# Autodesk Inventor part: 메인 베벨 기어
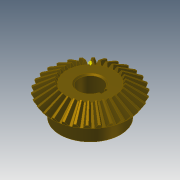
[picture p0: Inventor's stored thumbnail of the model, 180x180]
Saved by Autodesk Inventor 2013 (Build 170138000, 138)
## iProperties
Created: 2014-10
Part Number: 메인 베벨 기어
Material: 강철
Document SubType Name: Modeling
Designer: KYOUNG IL JANG
Categories: <?xml version="1.0" encoding="UTF-16"?> <MemberInstance><Categories><FamilyTemplate><FamilyTemplateParameter ValueType="xs:double" Id="1" ObjectReferenceKey="da
Mass: 269.24 g
Surface Area: 108.837 cm^2
Volume: 34.2981 cm^3
Density: 7.85 g/cm^3
CustomPartVersion: 1
Company: 한국ATC센터
Author: KYOUNG IL JANG
Revision Number: 1
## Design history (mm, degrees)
node "맨 위 점"
node "메쉬 평면2"
sketch "톱니 본체 스케치"
  geometry: L1 (0, 0)-(28.669, -21.997); L2 (28.669, -21.997)-(31.109, -18.336); L3 (31.109, -18.336)-(0, 0); L4 (30, -20)-(0, 0); L5 (17.219, -13.212)-(18.685, -11.013); L6 (28.669, -21.997)-(17.219, -13.212); L7 (31.109, -18.336)-(18.685, -11.013); L8 (0, -39.387)-(0, 6.564) reference; L9 (0, -20)-(31.109, -20)
  constraints: 16 end point, 4 point on line, 3 perpendicular, 2 collinear, 1 horizontal alignment, 1 vertical alignment
  dimensions: "d0" = 60 diameter of L4.start L8 (= da_de); "d1" = 57.33744 diameter of L1.end L8 (= da_dfe); "d2" = 62.2188 diameter of L2.end L8 (= da_dae); "d3" = 14.4 distance between parallel lines of L2 L5 (= da_b); "d4" = 18.3359 vertical distance of L2.end L1.start (= da_ve)
revolve "톱니 본체" sketch "톱니 본체 스케치" stored, may be unused: angle "d5" = 90 deg
node "시작점"
node "톱니 평면"
sketch "시작 스케치"
  geometry: L1 (0, -23.505)-(0, 10.645) reference; L2 (-0.709, -2.928)-(0.709, -2.928); A1 r 19.188 centre (-19.457, -7.014) between (-0.709, -2.928) and (-3.232, 3.229); A2 r 19.188 centre (19.457, -7.014) between (3.232, 3.229) and (0.709, -2.928); A3 r 57.403 centre (0, -54.083) between (3.232, 3.229) and (-3.232, 3.229); 1 further point
  constraints: 6 point on circle, 3 centre point, 3 symmetric about line, 2 end point, 1 coincident, 1 perpendicular, 1 other
  dimensions: "d7" = 19.18795 radius of A1 (= fd_rr); "d8" = 19.45712 horizontal distance of point (0, -54.083) A1.centre (= fd_x); "d9" = 47.06905 vertical distance of point (0, -54.083) A1.centre (= fd_y); "d57" = 57.40327 radius of A3 (= 0.5 x fd_dva + 0.3 x da_he); "d58" = 51.15527 distance from line of A3.centre L2 (= 0.5 x fd_dva - 1.12 x da_he)
node "끝점"
  node "끝 평면"
sketch "3D 스케치 오른쪽"
  node "Helical Curve Right" dims "d65" = 229.90621 (computed from da_dm, da_delta, da_beta), "d66" = 31.5, "d67" = 60 (= da_de), "d68" = -9.82794 (= -da_delta), "d69" = 8.10972 (computed from fd_loft, da_delta)
node "끝 평면 오른쪽"
sketch "끝 스케치 오른쪽"
  geometry: L1 (0, -41.54)-(0, 13.178) reference; L2 (-0.422, -1.69)-(0.422, -1.69); A1 r 11.427 centre (-11.587, -4.123) between (-0.422, -1.69) and (-1.925, 1.977); A2 r 11.427 centre (11.587, -4.123) between (1.925, 1.977) and (0.422, -1.69); A3 r 34.184 centre (0, -32.153) between (1.925, 1.977) and (-1.925, 1.977); 1 further point
  constraints: 6 point on circle, 3 centre point, 3 symmetric about line, 2 end point, 1 coincident, 1 perpendicular, 1 other
  dimensions: "d70" = 11.58699 horizontal distance of A3.centre A1.centre (computed from fd_x, fd_ratio); "d71" = 28.03028 vertical distance of point (0, -32.153) A1.centre (computed from fd_y, fd_ratio); "d72" = 11.4267 radius of A1 (computed from fd_rr, fd_ratio); "d73" = 30.46369 distance from line of point (0, -32.153) L2 (computed from d58, fd_ratio); "d74" = 34.18446 radius of A3 (computed from d57, fd_ratio)
feature "로프트 오른쪽" sketch "끝 스케치 오른쪽" dims "d75" = 0, "d77" = 0, "d79" = 0, "d80" = 90 deg, "d85" = 20, "d92" = 90 deg, "d93" = 90 deg, "da_teethtype" = 0 [user parameter]
sketch "3D 스케치 왼쪽"
  node "Helical Curve Left" dims "d26" = 229.90621 (computed from da_dm, da_delta, da_beta), "d27" = 8.10972 (computed from fd_loft, da_delta), "d28" = 60 (= da_de), "d29" = -9.82794 (= -da_delta)
node "끝 평면 왼쪽"
sketch "끝 스케치 왼쪽" dims "d56" = 10.3728 (derived)
  geometry: L1 (0, -43.753)-(0, 15.405) reference; L2 (-0.422, -1.678)-(0.422, -1.678); A1 r 11.427 centre (-11.587, -4.111) between (-0.422, -1.678) and (-1.925, 1.988); A2 r 11.427 centre (11.587, -4.111) between (1.925, 1.988) and (0.422, -1.678); A3 r 34.184 centre (0, -32.142) between (1.925, 1.988) and (-1.925, 1.988); 2 further points; 1 other entity
  constraints: 6 point on circle, 3 centre point, 3 symmetric about line, 2 end point, 1 coincident, 2 other
  dimensions: "d30" = 11.4267 radius of A1 (computed from fd_rr, fd_ratio); "d31" = 11.58699 horizontal distance of point (0, -32.142) A1.centre (computed from fd_x, fd_ratio); "d32" = 28.03028 vertical distance of A1.centre point (0, -32.142) (computed from fd_y, fd_ratio); "d61" = 34.18446 radius of A3 (computed from d57, fd_ratio); "d62" = 30.46369 distance from line of point (0, -32.142) L2 (computed from d58, fd_ratio)
feature "로프트 왼쪽" sketch "끝 스케치 왼쪽" dims "d35" = 0, "d37" = 0, "d39" = 0, "d40" = 90 deg, "d84" = 10, "d90" = 90 deg, "d91" = 90 deg, "da_teethtype" = 0 [user parameter]
sketch "본체 스케치"
  geometry: L1 (0, -35.038)-(0, -19.531) reference; L2 (28.669, -21.997)-(17.219, -13.212) reference; L3 (17.219, -13.212)-(0, -13.212); L4 (28.669, -21.997)-(0, -21.997)
  constraints: 4 end point, 2 perpendicular, 2 point on line
revolve "본체 고정" sketch "본체 스케치" stored, may be unused: angle "d46" = 90 deg
feature "피치 지름" dims angle "d47" = 90 deg
sketch "스케치8"
  geometry: C1 r 22.5 at (0, 0); 1 further point
  constraints: 1 centre point, 1 coincident
  dimensions: "d94" = 45 diameter of C1
extrude "돌출1" join sketch "스케치8" distance "d95" = 13; taper "d96" = 0 deg
sketch "스케치9"
  geometry: 1 further point
hole "구멍1" sketch "스케치9" at (0, 0) diameter "d97" = 17; stored, may be unused: countersink angle "d101" = 90 deg, drill point angle "d103" = 118 deg; dims "d98" = 6, "d99" = 4, "d100" = 2, "d102" = 8
sketch "스케치10"
  geometry: L1 (8.124, 2.5)-(10.8, 2.5); L2 (10.8, 2.5)-(10.8, -2.5); L3 (10.8, -2.5)-(8.124, -2.5); A1 r 8.5 centre (0, 0) between (8.124, 2.5) and (8.124, -2.5) reference; 1 further point
  constraints: 6 end point, 2 parallel, 2 point on circle, 1 horizontal, 1 perpendicular
  dimensions: "d104" = 5 distance of L1.end L2.end; "d112" = 19.3 dimension on A1 L2
extrude "돌출2" cut sketch "스케치10" stored distance "d106" = 10; taper "d107" = 0 deg
chamfer "모따기1" distance "d108" = 1; stored, may be unused: second distance "d109" = 2, angle "d110" = 45 deg
fillet "모깎기1" dims "d111" = 2
body "Solid1"
feature "로프트" dims "d17" = 0, "d18" = 90 deg, "d19" = 0, "d20" = 90 deg, "d89" = 0, "da_teethtype" = 0 [user parameter]
pattern_circular "원형 패턴" dims angle "d22" = 360 deg, "d88" = 0, "da_teethtype" = 0 [user parameter]
pattern_circular "원형 패턴 오른쪽" dims angle "d82" = 360 deg, "da_teethtype" = 0 [user parameter]
pattern_circular "원형 패턴 왼쪽" dims angle "d42" = 360 deg, "da_teethtype" = 0 [user parameter]
sketch "끝 스케치"
  geometry: L1 (0, -15.359)-(0, 6.983) reference; L2 (-0.422, -1.69)-(0.422, -1.69); A1 r 11.427 centre (-11.587, -4.123) between (-0.422, -1.69) and (-1.925, 1.977); A2 r 11.427 centre (11.587, -4.123) between (1.925, 1.977) and (0.422, -1.69); A3 r 34.184 centre (0, -32.153) between (1.925, 1.977) and (-1.925, 1.977); 1 further point
  constraints: 6 point on circle, 3 centre point, 3 symmetric about line, 2 end point, 1 coincident, 1 other
  dimensions: "d12" = 11.4267 radius of A1 (computed from fd_rr, fd_ratio); "d15" = 11.58699 horizontal distance of A1.centre point (0, -32.153) (computed from fd_x, fd_ratio); "d16" = 28.03028 vertical distance of A1.centre point (0, -32.153) (computed from fd_y, fd_ratio); "d59" = 34.18446 radius of A3 (computed from d57, fd_ratio); "d60" = 30.46369 distance from line of A3.centre L2 (computed from d58, fd_ratio)
sketch "Sketch6"
  geometry: L1 (30, -20)-(0, 0) reference; L2 (0, -37.8)-(0, 6.3) reference
body "Srf1"
other parameters: "da_b" = 14.4 [user parameter; used in 2 equation terms], "da_de" = 60 [user parameter; used in 4 equation terms], "da_dae" = 62.2188 [user parameter; used in 2 equation terms], "da_dfe" = 57.33744 [user parameter; used in 1 equation term], "da_le" = 36.05551 [user parameter; used in 1 equation term], "da_omega" = 90 deg [user parameter; used in 1 equation term], "da_beta" = 0 [user parameter; used in 2 equation terms], "da_delta" = 9.82794 [user parameter; used in 8 equation terms], "da_alpha" = 20 deg [user parameter; used in 2 equation terms], "da_he" = 4.4 [user parameter; used in 4 equation terms], "da_ve" = 18.3359 [user parameter; used in 1 equation term], "fd_dv" = 108.16654 (computed from da_de, da_delta) [user parameter; used in 1 equation term], "fd_dva" = 112.16654 (computed from da_dae, da_delta) [user parameter; used in 3 equation terms], "fd_dvb" = 101.6433 (computed from fd_dv, da_alpha) [user parameter; used in 2 equation terms], "da_zv" = 540.83269 [user parameter; used in 1 equation term], "fd_loft" = 14.62 (= da_b + 0.05 x da_he) [user parameter; used in 4 equation terms], "fd_ratio" = 5.95514 (computed from da_le, fd_loft) [user parameter; used in 15 equation terms], "fd_rr" = 19.18795 (computed from fd_dd, fd_dvb) [user parameter; used in 6 equation terms], "fd_angle" = 0.29367 (computed from da_zv) [user parameter; used in 4 equation terms], "fd_x1" = 1.58802 (computed from da_dvw, fd_angle) [user parameter; used in 1 equation term], "fd_y1" = 54.05995 (computed from da_dvw, fd_angle) [user parameter; used in 1 equation term], "fd_x2" = 17.8691 (computed from fd_rr, fd_angle2, fd_angle) [user parameter; used in 1 equation term], "fd_y2" = 6.9909 (computed from fd_rr, fd_angle2, fd_angle) [user parameter; used in 1 equation term], "fd_x" = 19.45712 (= fd_x1 + fd_x2) [user parameter; used in 4 equation terms], "fd_y" = 47.06905 (= fd_y1 - fd_y2) [user parameter; used in 4 equation terms], "fd_angle2" = 3.43555 (computed from fd_dvb, fd_dd, da_alpha) [user parameter; used in 2 equation terms], "fd_dd" = 108.64654 (= fd_dva - 0.8 x da_he) [user parameter; used in 2 equation terms], "da_dvw" = 108.16654 [user parameter; used in 2 equation terms], "d11" = 14.62 (= fd_loft), "da_dm" = 48.01848 [user parameter; used in 2 equation terms], "da_x" = 0 [user parameter], "da_m" = 2 [user parameter], "d48" = 0, "d49" = 0, "d50" = 90 deg (= da_omega), "d51" = 6 deg (computed from da_z), "d52" = 0, "d53" = 0, "d54" = 0
